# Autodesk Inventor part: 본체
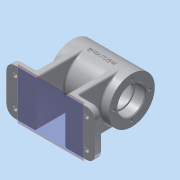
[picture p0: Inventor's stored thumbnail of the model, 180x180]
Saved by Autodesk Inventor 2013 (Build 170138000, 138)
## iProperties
Created: 2017-02
Part Number: 본체
Material: 알루미늄 6061
Document SubType Name: Modeling
Designer: Administrator
Density: 2.71 g/cm^3
Mass: 355.586 g
Surface Area: 423.837 cm^2
Volume: 131.213 cm^3
Author: Administrator
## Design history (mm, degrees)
sketch "스케치2"
  geometry: C1 r 27 at (0, 0); 1 further point
  constraints: 1 centre point, 1 coincident
  dimensions: "d0" = 54 diameter of C1
extrude "돌출1" new body sketch "스케치2" stored distance "d1" = 70; taper "d2" = 0 deg
sketch "스케치3"
  geometry: C1 r 16 at (0, 0); 1 further point
  constraints: 1 centre point, 1 coincident
  dimensions: "d3" = 32 diameter of C1
extrude "돌출2" cut sketch "스케치3" distance "d4" = 12; taper "d5" = 0 deg
sketch "스케치4"
  geometry: C1 r 27 at (0, 0) reference; C2 r 14 at (0, 0); 1 further point
  constraints: 1 centre point, 1 coincident
  dimensions: "d6" = 28 diameter of C2
extrude "돌출3" cut sketch "스케치4" distance "d7" = 3; taper "d8" = 0 deg
sketch "스케치6"
  geometry: C1 r 22 at (0, 0); 1 further point
  constraints: 1 centre point, 1 coincident
  dimensions: "d10" = 44 diameter of C1
extrude "돌출4" cut sketch "스케치6" distance "d11" = 40; taper "d12" = 0 deg
node "작업 평면1"
sketch "스케치7"
  geometry: L1 (5, 26.533)-(5, 32); L2 (5, 32)-(0, 32); L3 (0, 32)-(0, 27); A1 r 27 centre (0, 0) between (0, 27) and (5, 26.533) reference; 3 further points
  constraints: 6 end point, 2 point on circle, 1 parallel, 1 vertical alignment, 1 other
  dimensions: "d14" = 5 distance of L1.end L2.end; "d16" = 5 distance edge to line of A1 L2
revolve "회전1" sketch "스케치7" stored, may be unused: angle "d17" = 90 deg
hole "구멍1" diameter "d20" = 5.188; stored, may be unused: countersink angle "d24" = 90 deg, drill point angle "d26" = 118 deg; dims "d21" = 6, "d22" = 4, "d23" = 2, "d25" = 20, "d27" = 10, "d28" = 10
node "작업 평면2"
sketch "스케치8"
  geometry: L1 (0, 0)-(-13.5, -23.383); L2 (-13.5, -23.383)-(-15, -25.981); L3 (-15, -25.981)-(-9.804, -28.981); L4 (-9.804, -28.981)-(-7.966, -25.798); L5 (-7.966, -25.798)-(-13.162, -22.798); L6 (0, 0)-(0, -27); C1 r 16 at (0, 0) reference; C2 r 22 at (0, 0) reference; A1 r 27 centre (0, 0) between (-13.5, -23.383) and (-7.966, -25.798) reference
  constraints: 12 end point, 3 point on circle, 2 perpendicular, 1 collinear, 1 parallel, 1 point on line, 1 vertical
  dimensions: "d98" = 6 distance between parallel lines of L4 L2; "d100" = 30 distance from line of C1.centre L3; "d101" = 30 deg angle of L1 L6
  node "투영된 루프4"
node "작업 평면3"
sketch "스케치9"
  geometry: L1 (35, 27)-(-35, 27) reference; L2 (-35, 27)-(-35, -27) reference; L3 (35, -27)-(-35, -27) reference; L4 (35, -27)-(35, 27) reference; L5 (52, -17)-(52, 17); L6 (-52, 17)-(-52, -17); L7 (-52, -27)-(52, 27); L8 (52, -27)-(-52, 27); L9 (-17, 27)-(-17, -27); L10 (17, -27)-(17, 27); L11 (42, 27)-(17, 27); L12 (-17, 27)-(-42, 27); L13 (-42, -27)-(-17, -27); L14 (17, -27)-(42, -27); A1 r 10 centre (-42, 17) between (-42, 27) and (-52, 17); A2 r 10 centre (-42, -17) between (-52, -17) and (-42, -27); A3 r 10 centre (42, -17) between (42, -27) and (52, -17); A4 r 10 centre (42, 17) between (52, 17) and (42, 27); 1 further point
  constraints: 20 end point, 12 tangent, 8 point on circle, 5 parallel, 5 perpendicular, 4 centre point, 4 point on line, 3 equal radius, 2 horizontal, 2 midpoint
  dimensions: "d45" = 104 distance of L7.end L8.end; "d47" = 54 distance of L8.start L7.end; "d48" = 17 distance from line of L9 point (0, 0); "d49" = 17 distance from line of L10 point (0, 0); "d50" = 10 radius of A1
extrude "돌출5" join sketch "스케치9" distance "d51" = 8; taper "d52" = 0 deg
hole "구멍3" diameter "d55" = 5; stored, may be unused: countersink angle "d59" = 90 deg, drill point angle "d61" = 120 deg; dims "d53" = 10, "d54" = 10, "d56" = 6, "d57" = 9, "d58" = 3, "d60" = 30
sketch "스케치10"
  geometry: L1 (44, 8)-(10, 8) reference; L2 (0, 0)-(0, 8) reference; L3 (54, 0)-(54, 8) reference; L4 (-10.8, 0)-(64.8, 0) reference; L5 (0, 8)-(0, 60); L6 (54, 8)-(54, 60); L7 (5.5, 8)-(14.5, 8) reference; L8 (10, 8)-(0, 8) reference; L9 (39.5, 8)-(48.5, 8) reference; L10 (54, 8)-(44, 8) reference; A1 r 27 centre (27, 60) between (0, 60) and (54, 60) reference; 1 further point
  constraints: 4 end point, 2 point on circle, 1 parallel, 1 tangent
extrude "돌출6" join sketch "스케치10" distance "d68" = 8; taper "d69" = 0 deg
sketch "스케치11"
  geometry: A1 r 21 centre (0, 0) between (0, 21) and (-21, 0); 3 further points
  constraints: 4 point on circle, 1 centre point, 1 coincident
  dimensions: "d70" = 42 diameter of A1
hole "구멍4" sketch "스케치11" at (0, 21), (-21, 0), (0, -21), (21, 0.13) diameter "d72" = 3.242; stored, may be unused: countersink angle "d76" = 90 deg, drill point angle "d78" = 120 deg; dims "d73" = 8, "d74" = 4, "d75" = 2, "d77" = 10
fillet "모깎기1" dims "d79" = 2
chamfer "모따기1" distance "d80" = 1; stored, may be unused: second distance "d81" = 2, angle "d82" = 45 deg
fillet "모깎기2" dims "d83" = 0.3, "d84" = 2
node "작업 평면4"
sketch "스케치12"
  geometry: L1 (-35, 27)-(-35, -27) reference; L2 (-35, 27)-(35, 27) reference; 2 further points
  constraints: 1 other
  dimensions: "d86" = 27 distance from line of point (0, 0) L2; "d87" = 35 distance from line of L1 point (0, 0)
feature "엠보싱1" sketch "스케치12" dims "d11" = 40, "d12" = 0, "d88" = 0.5, "d89" = 0
revolve "회전3" stored, may be unused: angle "d102" = 90 deg
hole "구멍5" diameter "d105" = 5.188; stored, may be unused: countersink angle "d109" = 90 deg, drill point angle "d111" = 0 deg; dims "d106" = 6, "d107" = 4, "d108" = 2, "d110" = 30, "d112" = 10, "d113" = 10
node "솔리드1"
mirror "대칭1"
pattern_linear "직사각형 패턴1" dims "d64" = 84, "d67" = 34
mirror "대칭2"
mirror "대칭3"
node "투영된 루프1"
node "투영된 루프3"
other parameters: "d13" = -25, "d29" = -35
